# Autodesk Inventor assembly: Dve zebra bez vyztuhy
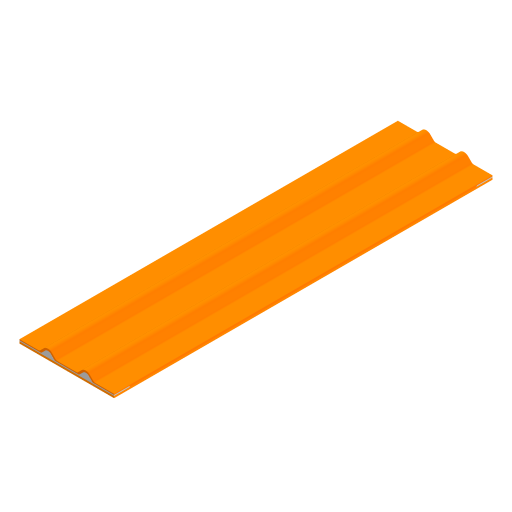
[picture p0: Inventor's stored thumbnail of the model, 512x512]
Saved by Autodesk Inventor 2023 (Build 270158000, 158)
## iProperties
Created: 2025-03
Part Number: Dve zebra bez vyztuhy
Document SubType Name: Assembly
Designer: tomik
Author: tomik
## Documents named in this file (4)
- C:\Users\tomik\Desktop\Diplomka\Struktury\Desky\Struktury_20.3\Dvě žebra bez výztuhy\Dve zebra bez vyztuhy.iam
- C:\Users\tomik\Desktop\Diplomka\Struktury\Desky\Struktury_20.3\Dvě žebra bez výztuhy\Spodni tkanina 50x200.ipt
- C:\Users\tomik\Desktop\Diplomka\Struktury\Desky\Struktury_20.3\Dvě žebra bez výztuhy\Horni tkanina.ipt
- C:\Users\tomik\Desktop\Diplomka\Struktury\Desky\Struktury_20.3\Dvě žebra bez výztuhy\Zebra bez vyztuhy + mustek.ipt
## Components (3 placed, 3 different names)
1. Spodni tkanina 50x200:1 — Proti sobě:1, Proti sobě:2, Stejný směr:1, Proti sobě:6, Stejný směr:5, Stejný směr:6, Proti sobě:7, Proti sobě:8, Proti sobě:9
2. Horni tkanina:1 — Proti sobě:6, Stejný směr:5, Stejný směr:6
3. Zebra bez vyztuhy + mustek:1 — Proti sobě:7, Proti sobě:8, Proti sobě:9
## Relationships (9: Mate 6, Flush 3)
- Proti sobě:1 [Mate]: Spodni tkanina 50x200:1
- Proti sobě:2 [Mate]: Spodni tkanina 50x200:1
- Stejný směr:1 [Flush]: Spodni tkanina 50x200:1
- Proti sobě:6 [Mate]: Spodni tkanina 50x200:1 ↔ Horni tkanina:1
- Stejný směr:5 [Flush]: Spodni tkanina 50x200:1 ↔ Horni tkanina:1
- Stejný směr:6 [Flush]: Spodni tkanina 50x200:1 ↔ Horni tkanina:1
- Proti sobě:7 [Mate]: Spodni tkanina 50x200:1 ↔ Zebra bez vyztuhy + mustek:1
- Proti sobě:8 [Mate]: Spodni tkanina 50x200:1 ↔ Zebra bez vyztuhy + mustek:1
- Proti sobě:9 [Mate]: Spodni tkanina 50x200:1 ↔ Zebra bez vyztuhy + mustek:1
